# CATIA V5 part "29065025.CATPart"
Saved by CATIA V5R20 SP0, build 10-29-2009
Part number: 29065025
Definition: NONE
Nomenclature: 29065025
Source: Unknown
Description: 29065025
Bounding box of the stored display mesh (mm): x -12.5 to 44.548, y -46.5 to 81.048, z -36.5 to 36.5
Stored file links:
  C:\Users\Utente\Desktop\IO LAVORO\3D X SITO CF\X SITO\PLASTICA\RF1\29065025.CATPart
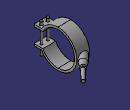
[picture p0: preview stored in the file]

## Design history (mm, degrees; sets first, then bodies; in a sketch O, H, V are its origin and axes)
Body1 "29065025" (main body)
  Solid1: solid without history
